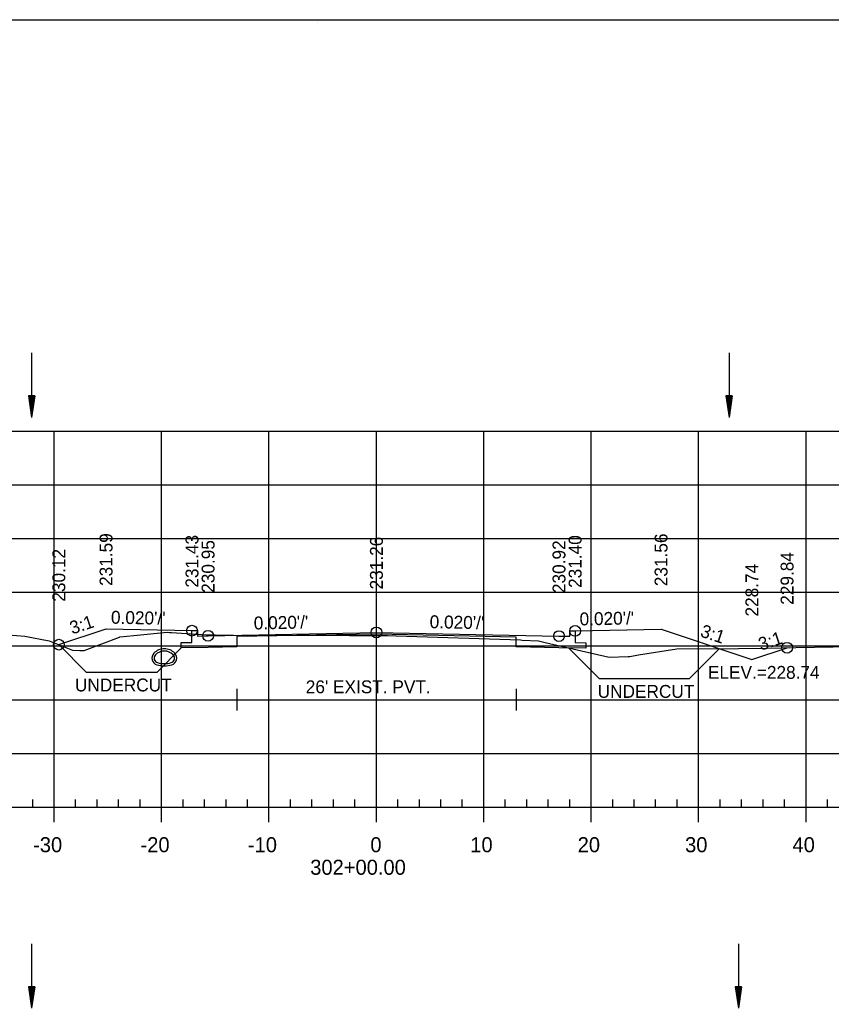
# Model space of a CAD drawing. Extents: x 1386544 to 1388153, y 379785 to 390999.
# Drawn here: x 1386681.7 to 1386757.2, y 384395.8 to 384488 of the extents above; entities that cross this region are included whole.
import ezdxf

# ---------------------------------------------------------------- set-up
doc = ezdxf.new("R2010")
doc.units = 0
for name, color, linetype in [('R_Alt Surface', 7, 'Continuous'), ('R_Axis', 7, 'Continuous'), ('R_Axis Annot', 7, 'Continuous'), ('R_Border', 7, 'Continuous'), ('R_Dimension', 7, 'Continuous'), ('R_Exist Surface', 7, 'Continuous'), ('R_Fin Surface', 7, 'Continuous'), ('R_Fin Surface Annot', 7, 'Continuous'), ('R_Grid', 7, 'Continuous'), ('R_No Plot', 7, 'Continuous'), ('R_Water', 7, 'Continuous')]:
    doc.layers.add(name, color=color, linetype=linetype)

msp = doc.modelspace()

# ---------------------------------------------------------------- linework, layer by layer
at = {"layer": 'R_Alt Surface'}
for points in [[(1386733.37, 384431.154), (1386733.37, 384430.06), (1386734.37, 384430.04), (1386734.37, 384429.54), (1386731.87, 384429.59), (1386727.87, 384429.668), (1386727.87, 384430.584), (1386714.87, 384430.844), (1386701.87, 384430.639), (1386701.87, 384429.668), (1386699.199, 384429.617), (1386696.699, 384429.567), (1386696.699, 384430.067), (1386697.699, 384430.087), (1386697.699, 384431.18)], [(1386701.87, 384425.751), (1386701.87, 384423.751)], [(1386727.87, 384425.751), (1386727.87, 384423.751)], [(1386701.87, 384424.751), (1386727.87, 384424.751)]]:
    msp.add_lwpolyline(points, dxfattribs=at)
at = {"layer": 'R_Axis'}
for p, q in [((1386682.87, 384414.751), (1386682.87, 384415.451)), ((1386686.87, 384414.751), (1386686.87, 384415.451)), ((1386688.87, 384414.751), (1386688.87, 384415.451)), ((1386690.87, 384414.751), (1386690.87, 384415.451)), ((1386692.87, 384414.751), (1386692.87, 384415.451)), ((1386696.87, 384414.751), (1386696.87, 384415.451)), ((1386698.87, 384414.751), (1386698.87, 384415.451)), ((1386700.87, 384414.751), (1386700.87, 384415.451)), ((1386702.87, 384414.751), (1386702.87, 384415.451)), ((1386706.87, 384414.751), (1386706.87, 384415.451)), ((1386708.87, 384414.751), (1386708.87, 384415.451)), ((1386710.87, 384414.751), (1386710.87, 384415.451)), ((1386712.87, 384414.751), (1386712.87, 384415.451)), ((1386716.87, 384414.751), (1386716.87, 384415.451)), ((1386718.87, 384414.751), (1386718.87, 384415.451)), ((1386720.87, 384414.751), (1386720.87, 384415.451)), ((1386722.87, 384414.751), (1386722.87, 384415.451)), ((1386726.87, 384414.751), (1386726.87, 384415.451)), ((1386728.87, 384414.751), (1386728.87, 384415.451)), ((1386730.87, 384414.751), (1386730.87, 384415.451)), ((1386732.87, 384414.751), (1386732.87, 384415.451)), ((1386736.87, 384414.751), (1386736.87, 384415.451)), ((1386738.87, 384414.751), (1386738.87, 384415.451)), ((1386740.87, 384414.751), (1386740.87, 384415.451)), ((1386742.87, 384414.751), (1386742.87, 384415.451)), ((1386746.87, 384414.751), (1386746.87, 384415.451)), ((1386748.87, 384414.751), (1386748.87, 384415.451)), ((1386750.87, 384414.751), (1386750.87, 384415.451)), ((1386752.87, 384414.751), (1386752.87, 384415.451)), ((1386756.87, 384414.751), (1386756.87, 384415.451)), ((1386569.87, 384414.751), (1386859.87, 384414.751)), ((1386684.87, 384413.351), (1386684.87, 384414.751)), ((1386694.87, 384413.351), (1386694.87, 384414.751)), ((1386704.87, 384413.351), (1386704.87, 384414.751)), ((1386714.87, 384413.351), (1386714.87, 384414.751)), ((1386724.87, 384413.351), (1386724.87, 384414.751)), ((1386734.87, 384413.351), (1386734.87, 384414.751)), ((1386744.87, 384413.351), (1386744.87, 384414.751)), ((1386754.87, 384413.351), (1386754.87, 384414.751))]:
    msp.add_line(p, q, dxfattribs=at)
at = {"layer": 'R_Border'}
for p, q in [((1386556.87, 384488.044), (1386873.05, 384488.044)), ((1386709.39, 384487.784), (1386709.39, 384487.784)), ((1386709.39, 384487.784), (1386709.39, 384487.784))]:
    msp.add_line(p, q, dxfattribs=at)
at = {"layer": 'R_Dimension'}
for p, q in [((1386685.302, 384429.875), (1386687.858, 384427.319)), ((1386696.699, 384429.567), (1386694.451, 384427.319)), ((1386732.769, 384429.572), (1386735.62, 384426.721)), ((1386746.801, 384429.504), (1386744.018, 384426.721))]:
    msp.add_line(p, q, dxfattribs=at)
for points in [[(1386687.858, 384427.319), (1386694.451, 384427.319)], [(1386735.62, 384426.721), (1386744.018, 384426.721)]]:
    msp.add_lwpolyline(points, dxfattribs=at)
at = {"layer": 'R_Exist Surface'}
msp.add_lwpolyline([(1386678.997, 384430.914), (1386682.13, 384430.65), (1386684.416, 384430.232), (1386686.587, 384429.357), (1386687.25, 384429.335), (1386687.665, 384429.319), (1386690.943, 384430.578), (1386690.985, 384430.6), (1386692.274, 384430.715), (1386695.405, 384431.024), (1386695.616, 384431.007), (1386695.774, 384430.995), (1386695.797, 384431), (1386699.067, 384430.788), (1386699.865, 384430.775), (1386701.115, 384430.77), (1386701.55, 384430.772), (1386712.38, 384430.731), (1386715.897, 384430.724), (1386716.718, 384430.696), (1386728.281, 384430.316), (1386728.43, 384430.307), (1386729.953, 384430.215), (1386730.598, 384430.06), (1386736.555, 384428.721), (1386738.308, 384428.762), (1386738.475, 384428.774), (1386739.28, 384428.918), (1386742.855, 384429.483), (1386748.575, 384429.513), (1386751.238, 384429.557), (1386753.932, 384429.599), (1386762.57, 384429.775)], dxfattribs=at)
at = {"layer": 'R_Fin Surface'}
msp.add_lwpolyline([(1386685.302, 384429.875), (1386689.699, 384431.34), (1386697.699, 384431.18), (1386698.199, 384431.18), (1386698.2, 384430.68), (1386699.199, 384430.7), (1386714.87, 384431.014), (1386731.87, 384430.674), (1386732.869, 384430.654), (1386732.87, 384431.154), (1386733.37, 384431.154), (1386741.37, 384431.314), (1386749.829, 384428.494), (1386753.105, 384429.586)], dxfattribs=at)
at = {"layer": 'R_Grid'}
for p, q in [((1386569.87, 384449.751), (1386859.87, 384449.751)), ((1386684.87, 384414.751), (1386684.87, 384449.751)), ((1386694.87, 384414.751), (1386694.87, 384449.751)), ((1386704.87, 384414.751), (1386704.87, 384449.751)), ((1386714.87, 384414.751), (1386714.87, 384449.751)), ((1386724.87, 384414.751), (1386724.87, 384449.751)), ((1386734.87, 384414.751), (1386734.87, 384449.751)), ((1386744.87, 384414.751), (1386744.87, 384449.751)), ((1386754.87, 384414.751), (1386754.87, 384449.751)), ((1386569.87, 384444.751), (1386859.87, 384444.751)), ((1386569.87, 384439.751), (1386859.87, 384439.751)), ((1386569.87, 384434.751), (1386859.87, 384434.751)), ((1386569.87, 384429.751), (1386859.87, 384429.751)), ((1386569.87, 384424.751), (1386859.87, 384424.751)), ((1386569.87, 384419.751), (1386859.87, 384419.751)), ((1386569.87, 384414.751), (1386859.87, 384414.751))]:
    msp.add_line(p, q, dxfattribs=at)
at = {"layer": 'R_No Plot'}
msp.add_lwpolyline([(1386790.79, 384488.044), (1386810.41, 384488.044), (1386810.41, 384478.164), (1386826.523, 384478.164), (1386849.722, 384478.164), (1386849.722, 384453.832), (1386873.05, 384453.832), (1386873.05, 384282.584), (1386556.87, 384282.584), (1386556.87, 384488.044)], close=True, dxfattribs=at)
for centre in [(1386697.699, 384431.18), (1386699.199, 384430.7), (1386714.87, 384431.014), (1386731.87, 384430.674), (1386733.37, 384431.154), (1386685.302, 384429.875), (1386753.105, 384429.586)]:
    msp.add_circle(centre, 0.5, dxfattribs=at)
for centre, radius, start, end in [((1386694.612, 384428.622), 0.646, 136.35152, 253.95293), ((1386695.124, 384428.133), 1.354, 43.64848, 136.35152), ((1386695.637, 384428.622), 0.646, 286.04707, 43.64848), ((1386695.124, 384430.404), 2.5, 253.95293, 286.04707)]:
    msp.add_arc(centre, radius, start, end, dxfattribs=at)
at = {"layer": 'R_Water'}
for p, q in [((1386682.773, 384457.034), (1386682.773, 384451.034)), ((1386747.708, 384457.034), (1386747.708, 384451.034)), ((1386682.473, 384453.034), (1386682.773, 384451.034)), ((1386683.073, 384453.034), (1386682.473, 384453.034)), ((1386682.473, 384453.034), (1386682.773, 384451.034)), ((1386683.073, 384453.034), (1386682.473, 384453.034)), ((1386682.523, 384453.034), (1386682.773, 384451.368)), ((1386682.523, 384453.034), (1386682.773, 384451.368)), ((1386682.574, 384453.034), (1386682.773, 384451.712)), ((1386682.574, 384453.034), (1386682.773, 384451.712)), ((1386682.624, 384453.034), (1386682.773, 384452.045)), ((1386682.624, 384453.034), (1386682.773, 384452.045)), ((1386682.675, 384453.034), (1386682.773, 384452.384)), ((1386682.675, 384453.034), (1386682.773, 384452.384)), ((1386682.726, 384453.034), (1386682.773, 384452.718)), ((1386682.726, 384453.034), (1386682.773, 384452.718)), ((1386683.073, 384453.034), (1386682.773, 384451.034)), ((1386682.87, 384453.034), (1386682.773, 384452.384)), ((1386682.972, 384453.034), (1386682.773, 384451.712)), ((1386683.023, 384453.034), (1386682.773, 384451.368)), ((1386682.922, 384453.034), (1386682.773, 384452.045)), ((1386682.82, 384453.034), (1386682.773, 384452.718)), ((1386683.073, 384453.034), (1386682.773, 384451.034)), ((1386682.87, 384453.034), (1386682.773, 384452.384)), ((1386682.972, 384453.034), (1386682.773, 384451.712)), ((1386683.023, 384453.034), (1386682.773, 384451.368)), ((1386682.922, 384453.034), (1386682.773, 384452.045)), ((1386682.82, 384453.034), (1386682.773, 384452.718)), ((1386747.408, 384453.034), (1386747.708, 384451.034)), ((1386748.008, 384453.034), (1386747.408, 384453.034)), ((1386747.408, 384453.034), (1386747.708, 384451.034)), ((1386748.008, 384453.034), (1386747.408, 384453.034)), ((1386747.458, 384453.034), (1386747.708, 384451.368)), ((1386747.458, 384453.034), (1386747.708, 384451.368)), ((1386747.509, 384453.034), (1386747.708, 384451.712)), ((1386747.509, 384453.034), (1386747.708, 384451.712)), ((1386747.559, 384453.034), (1386747.708, 384452.045)), ((1386747.559, 384453.034), (1386747.708, 384452.045)), ((1386747.61, 384453.034), (1386747.708, 384452.384)), ((1386747.61, 384453.034), (1386747.708, 384452.384)), ((1386747.661, 384453.034), (1386747.708, 384452.718)), ((1386747.661, 384453.034), (1386747.708, 384452.718)), ((1386748.008, 384453.034), (1386747.708, 384451.034)), ((1386747.805, 384453.034), (1386747.708, 384452.384)), ((1386747.907, 384453.034), (1386747.708, 384451.712)), ((1386747.958, 384453.034), (1386747.708, 384451.368)), ((1386747.857, 384453.034), (1386747.708, 384452.045)), ((1386747.755, 384453.034), (1386747.708, 384452.718)), ((1386748.008, 384453.034), (1386747.708, 384451.034)), ((1386747.805, 384453.034), (1386747.708, 384452.384)), ((1386747.907, 384453.034), (1386747.708, 384451.712)), ((1386747.958, 384453.034), (1386747.708, 384451.368)), ((1386747.857, 384453.034), (1386747.708, 384452.045)), ((1386747.755, 384453.034), (1386747.708, 384452.718)), ((1386682.773, 384402.034), (1386682.773, 384396.034)), ((1386748.573, 384402.034), (1386748.573, 384396.034)), ((1386682.473, 384398.034), (1386682.773, 384396.034)), ((1386683.073, 384398.034), (1386682.473, 384398.034)), ((1386682.473, 384398.034), (1386682.773, 384396.034)), ((1386683.073, 384398.034), (1386682.473, 384398.034)), ((1386682.523, 384398.034), (1386682.773, 384396.368)), ((1386682.523, 384398.034), (1386682.773, 384396.368)), ((1386682.574, 384398.034), (1386682.773, 384396.712)), ((1386682.574, 384398.034), (1386682.773, 384396.712)), ((1386682.624, 384398.034), (1386682.773, 384397.045)), ((1386682.624, 384398.034), (1386682.773, 384397.045)), ((1386682.675, 384398.034), (1386682.773, 384397.384)), ((1386682.675, 384398.034), (1386682.773, 384397.384)), ((1386682.726, 384398.034), (1386682.773, 384397.718)), ((1386682.726, 384398.034), (1386682.773, 384397.718)), ((1386683.073, 384398.034), (1386682.773, 384396.034)), ((1386682.87, 384398.034), (1386682.773, 384397.384)), ((1386682.972, 384398.034), (1386682.773, 384396.712)), ((1386683.023, 384398.034), (1386682.773, 384396.368)), ((1386682.922, 384398.034), (1386682.773, 384397.045)), ((1386682.82, 384398.034), (1386682.773, 384397.718)), ((1386683.073, 384398.034), (1386682.773, 384396.034)), ((1386682.87, 384398.034), (1386682.773, 384397.384)), ((1386682.972, 384398.034), (1386682.773, 384396.712)), ((1386683.023, 384398.034), (1386682.773, 384396.368)), ((1386682.922, 384398.034), (1386682.773, 384397.045)), ((1386682.82, 384398.034), (1386682.773, 384397.718)), ((1386748.273, 384398.034), (1386748.573, 384396.034)), ((1386748.873, 384398.034), (1386748.273, 384398.034)), ((1386748.273, 384398.034), (1386748.573, 384396.034)), ((1386748.873, 384398.034), (1386748.273, 384398.034)), ((1386748.323, 384398.034), (1386748.573, 384396.368)), ((1386748.323, 384398.034), (1386748.573, 384396.368)), ((1386748.374, 384398.034), (1386748.573, 384396.712)), ((1386748.374, 384398.034), (1386748.573, 384396.712)), ((1386748.424, 384398.034), (1386748.573, 384397.045)), ((1386748.424, 384398.034), (1386748.573, 384397.045)), ((1386748.475, 384398.034), (1386748.573, 384397.384)), ((1386748.475, 384398.034), (1386748.573, 384397.384)), ((1386748.526, 384398.034), (1386748.573, 384397.718)), ((1386748.526, 384398.034), (1386748.573, 384397.718)), ((1386748.873, 384398.034), (1386748.573, 384396.034)), ((1386748.67, 384398.034), (1386748.573, 384397.384)), ((1386748.772, 384398.034), (1386748.573, 384396.712)), ((1386748.823, 384398.034), (1386748.573, 384396.368)), ((1386748.722, 384398.034), (1386748.573, 384397.045)), ((1386748.62, 384398.034), (1386748.573, 384397.718)), ((1386748.873, 384398.034), (1386748.573, 384396.034)), ((1386748.67, 384398.034), (1386748.573, 384397.384)), ((1386748.772, 384398.034), (1386748.573, 384396.712)), ((1386748.823, 384398.034), (1386748.573, 384396.368)), ((1386748.722, 384398.034), (1386748.573, 384397.045)), ((1386748.62, 384398.034), (1386748.573, 384397.718))]:
    msp.add_line(p, q, dxfattribs=at)
for centre, radius, start, end in [((1386695.124, 384428.133), 1.146, 43.64848, 136.35152), ((1386694.612, 384428.622), 0.438, 136.35152, 253.95293), ((1386695.124, 384430.404), 2.292, 253.95293, 286.04707), ((1386695.637, 384428.622), 0.438, 286.04707, 43.64848)]:
    msp.add_arc(centre, radius, start, end, dxfattribs=at)

# ---------------------------------------------------------------- texts
at = {"layer": 'R_Axis Annot'}
for s, p in [('-30', (1386682.909, 384410.551)), ('-20', (1386692.909, 384410.551)), ('-10', (1386702.909, 384410.551)), ('0', (1386714.309, 384410.551)), ('10', (1386723.609, 384410.551)), ('20', (1386733.609, 384410.551)), ('30', (1386743.609, 384410.551)), ('40', (1386753.609, 384410.551)), ('302+00.00', (1386708.709, 384408.451))]:
    msp.add_text(s, height=1.4, dxfattribs=at).set_placement(p)
at = {"layer": 'R_Dimension'}
for p in [(1386686.803, 384425.519), (1386735.468, 384424.921)]:
    msp.add_text('UNDERCUT', height=1.2, dxfattribs=at).set_placement(p)
at = {"layer": 'R_Fin Surface Annot'}
for s, rotation, p in [('231.59', 90, (1386690.299, 384435.34)), ('231.56', 90, (1386741.97, 384435.314)), ('231.43', 90, (1386698.299, 384435.18)), ('230.95', 90, (1386699.799, 384434.7)), ('231.26', 90, (1386715.47, 384435.014)), ('230.92', 90, (1386732.47, 384434.674)), ('231.40', 90, (1386733.97, 384435.154)), ('230.12', 90, (1386685.902, 384433.875)), ('229.84', 90, (1386753.705, 384433.586)), ('228.74', 90, (1386750.429, 384432.494)), ("0.020'/'", 358.85424, (1386690.147, 384431.831)), ("0.020'/'", 1.14576, (1386733.799, 384431.662)), ('3:1', 18.43493, (1386686.553, 384430.819)), ("0.020'/'", 1.14576, (1386703.463, 384431.286)), ("0.020'/'", 358.85424, (1386719.819, 384431.415)), ('3:1', 341.56507, (1386744.949, 384430.655)), ('3:1', 18.43493, (1386750.674, 384429.303))]:
    msp.add_text(s, height=1.2, rotation=rotation, dxfattribs=at).set_placement(p)
msp.add_text('ELEV.=228.74', height=1.2, dxfattribs=at).set_placement((1386745.739, 384426.694))
at = {"layer": 'R_No Plot'}
for p in [(1386689.656, 384431.29), (1386741.328, 384431.264)]:
    msp.add_text('+', height=0.1, dxfattribs=at).set_placement(p)
at = {"layer": 'R_Water'}
msp.add_text("26' EXIST. PVT.", height=1.2, dxfattribs=at).set_placement((1386708.294, 384425.351))

doc.saveas('drawing.dxf')
